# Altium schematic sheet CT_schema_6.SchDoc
size 287 x 160 mm
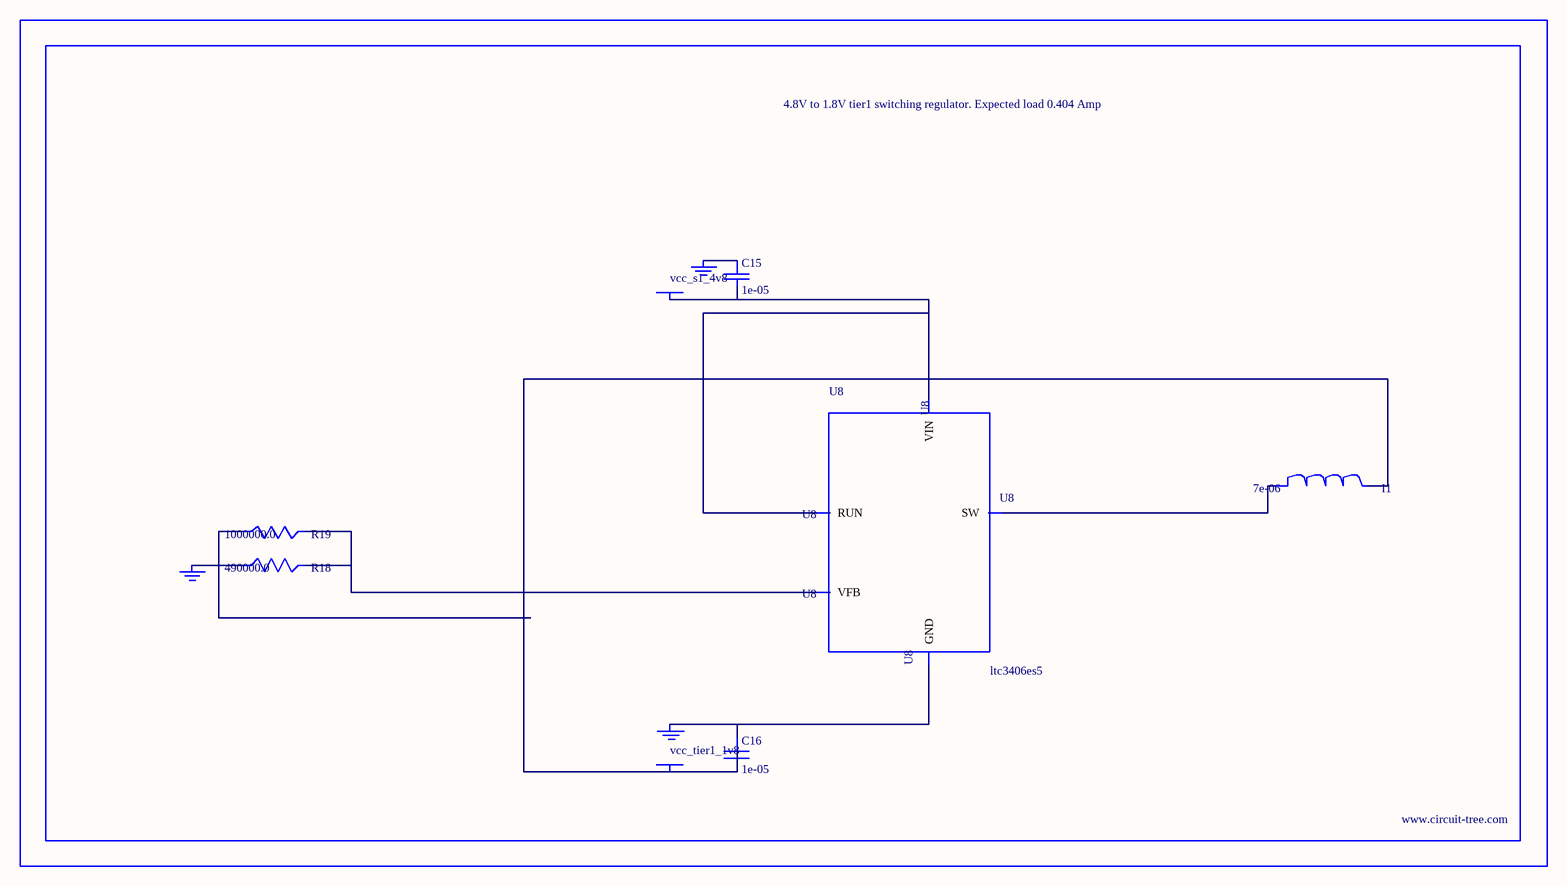
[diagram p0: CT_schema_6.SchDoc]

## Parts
BORDER5  (no value)
C15  1e-05  [C0805]
C16  1e-05  [C0805]
GND_INSTANCE_5_0  (no value)
GND_INSTANCE_5_1  (no value)
GND_INSTANCE_5_2  (no value)
I1  7e-06  [DR1040]
POWER_INSTANCE_5_0  vcc_tier1_1v8
POWER_INSTANCE_5_1  vcc_s1_4v8
R18  490000.0  [R0603]
R19  1000000.0  [R0603]
U8  ltc3406es5  [TSOT-23-5]

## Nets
NetC15_1: C15.1 GND_INSTANCE_5_1.0(GND)
NetC15_2: C15.2 POWER_INSTANCE_5_1.0(PWR) U8.1(RUN) U8.4(VIN)
NetC16_1: C16.1 GND_INSTANCE_5_0.0(GND) U8.2(GND)
NetC16_2: C16.2 I1.2 POWER_INSTANCE_5_0.0(PWR) R19.1
NetGND_INSTANCE_5_2_0: GND_INSTANCE_5_2.0(GND) R18.1
NetI1_1: I1.1 U8.3(SW)
NetR18_2: R18.2 R19.2 U8.5(VFB)

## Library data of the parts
BORDER5 = BORDER_PAGE5
C15 C16 = C0805C106K8RACTU
GND_INSTANCE_5_0-GND_INSTANCE_5_2 = GND
I1 = DR1040-7R0-R
POWER_INSTANCE_5_0 POWER_INSTANCE_5_1 = PWR
R18 = R18
R19 = RC0603JR-071ML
